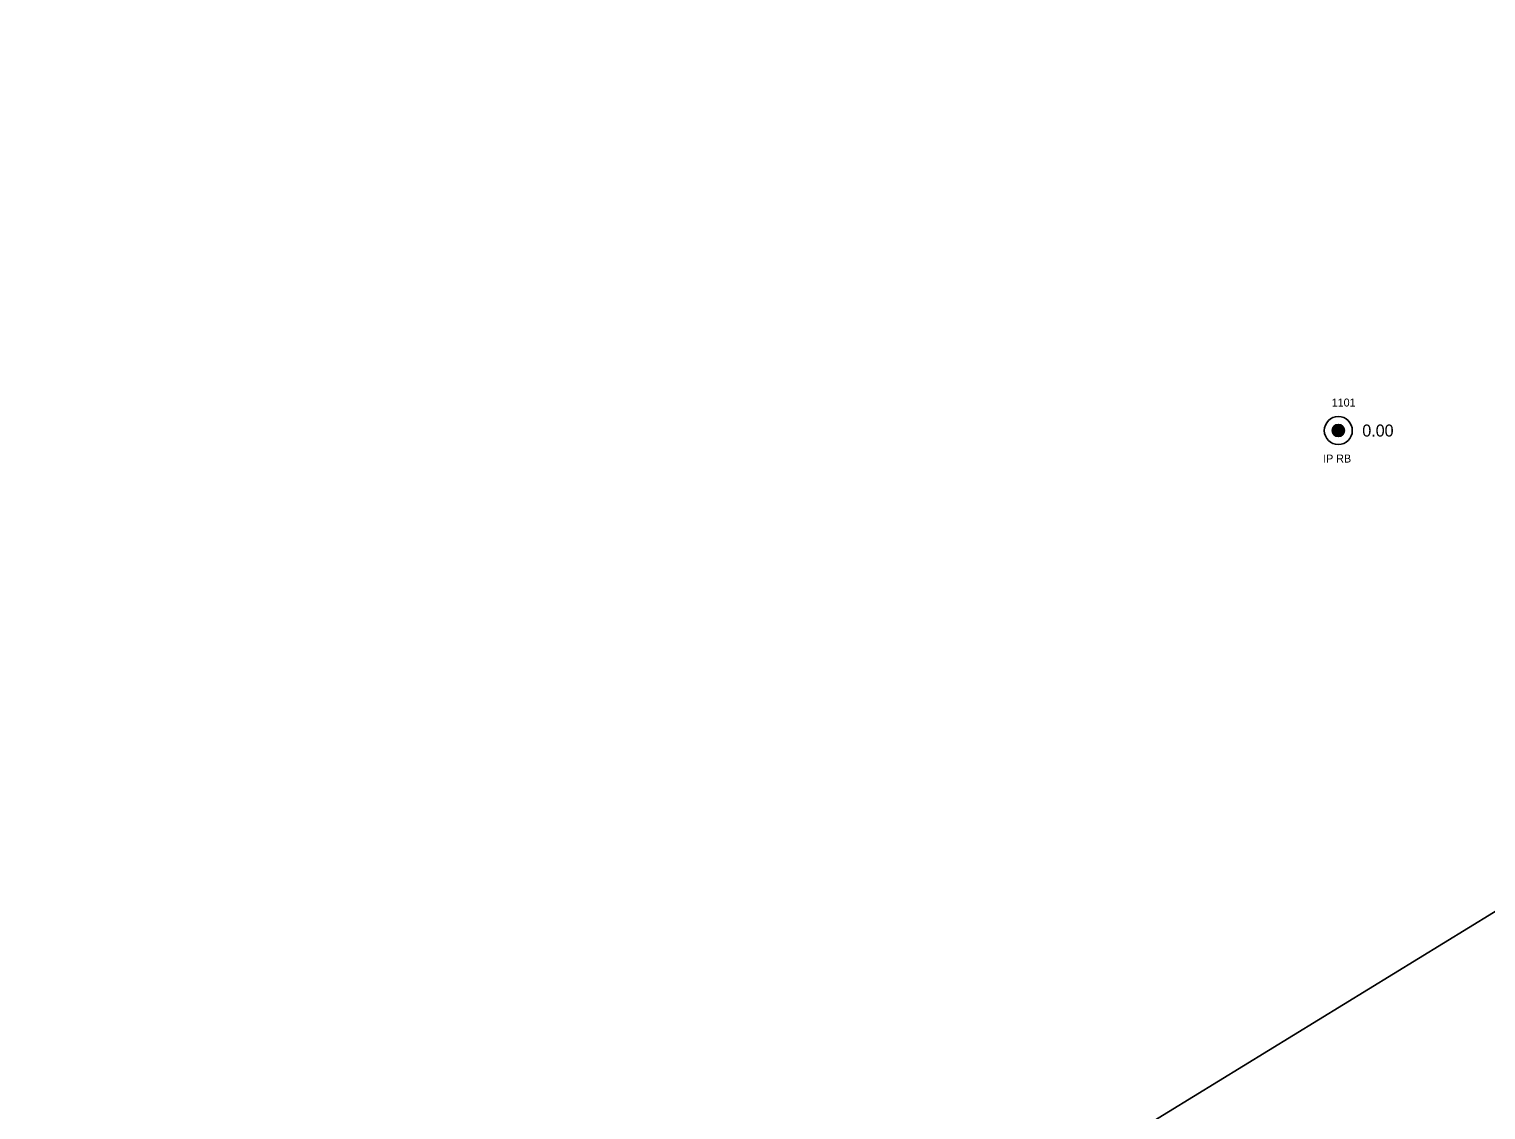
# Model space of a CAD drawing. Extents: x 1575382 to 1578175, y 1099175 to 1101955.
# Drawn here: x 1575942.3 to 1576124.3, y 1099553 to 1099688.1 of the extents above; entities that cross this region are included whole.
import ezdxf

# ---------------------------------------------------------------- set-up
doc = ezdxf.new("R2010")
doc.units = 0
for name, color, linetype in [('RD_EX_DV_Prop_txCode', 7, 'Continuous'), ('RD_EX_DV_PropPin', 7, 'Continuous'), ('RD_EX_TX_DV_Prop_ELEV', 7, 'Continuous'), ('RD_EX_UT', 7, 'Continuous'), ('RD_SMD_Locator', 7, 'Continuous')]:
    doc.layers.add(name, color=color, linetype=linetype)

msp = doc.modelspace()

# ---------------------------------------------------------------- linework, layer by layer
at = {"layer": 'RD_EX_DV_PropPin'}
for p, q in [((1576105.13, 1099637.72), (1576105.13, 1099638.11)), ((1576105.17, 1099637.62), (1576105.17, 1099638.22)), ((1576105.2, 1099637.55), (1576105.2, 1099638.29)), ((1576105.24, 1099637.49), (1576105.24, 1099638.35)), ((1576105.27, 1099637.44), (1576105.27, 1099638.39)), ((1576105.31, 1099637.4), (1576105.31, 1099638.43)), ((1576105.34, 1099637.37), (1576105.34, 1099638.47)), ((1576105.38, 1099637.34), (1576105.38, 1099638.5)), ((1576105.41, 1099637.31), (1576105.41, 1099638.53)), ((1576105.45, 1099637.28), (1576105.45, 1099638.55)), ((1576105.48, 1099637.26), (1576105.48, 1099638.58)), ((1576105.52, 1099637.24), (1576105.52, 1099638.59)), ((1576105.55, 1099637.23), (1576105.55, 1099638.61)), ((1576105.59, 1099637.21), (1576105.59, 1099638.63)), ((1576105.62, 1099637.2), (1576105.62, 1099638.64)), ((1576105.66, 1099637.19), (1576105.66, 1099638.65)), ((1576105.69, 1099637.18), (1576105.69, 1099638.66)), ((1576105.73, 1099637.17), (1576105.73, 1099638.67)), ((1576105.76, 1099637.17), (1576105.76, 1099638.67)), ((1576105.8, 1099637.16), (1576105.8, 1099638.68)), ((1576105.83, 1099637.16), (1576105.83, 1099638.68)), ((1576105.87, 1099637.16), (1576105.87, 1099638.68)), ((1576105.9, 1099637.16), (1576105.9, 1099638.68)), ((1576105.94, 1099637.16), (1576105.94, 1099638.68)), ((1576105.97, 1099637.17), (1576105.97, 1099638.67)), ((1576106.01, 1099637.17), (1576106.01, 1099638.67)), ((1576106.04, 1099637.18), (1576106.04, 1099638.66)), ((1576106.08, 1099637.19), (1576106.08, 1099638.65)), ((1576106.11, 1099637.2), (1576106.11, 1099638.64)), ((1576106.15, 1099637.21), (1576106.15, 1099638.63)), ((1576106.18, 1099637.23), (1576106.18, 1099638.61)), ((1576106.22, 1099637.24), (1576106.22, 1099638.59)), ((1576106.25, 1099637.26), (1576106.25, 1099638.58)), ((1576106.29, 1099637.28), (1576106.29, 1099638.55)), ((1576106.32, 1099637.31), (1576106.32, 1099638.53)), ((1576106.36, 1099637.34), (1576106.36, 1099638.5)), ((1576106.39, 1099637.37), (1576106.39, 1099638.47)), ((1576106.43, 1099637.4), (1576106.43, 1099638.43)), ((1576106.46, 1099637.44), (1576106.46, 1099638.39)), ((1576106.5, 1099637.49), (1576106.5, 1099638.35)), ((1576106.53, 1099637.55), (1576106.53, 1099638.29)), ((1576106.57, 1099637.62), (1576106.57, 1099638.22)), ((1576106.6, 1099637.72), (1576106.6, 1099638.11))]:
    msp.add_line(p, q, dxfattribs=at)
for radius in [1.75, 0.761]:
    msp.add_circle((1576105.87, 1099637.92), radius, dxfattribs=at)
at = {"layer": 'RD_EX_UT'}
msp.add_line((1575942.28, 1099465.48), (1576305.27, 1099688.09), dxfattribs=at)
at = {"layer": 'RD_SMD_Locator'}
msp.add_circle((1576105.87, 1099637.92), 0.15, dxfattribs=at)

# ---------------------------------------------------------------- texts
at = {"layer": 'RD_EX_DV_Prop_txCode'}
for s, p in [('1101', (1576105.05, 1099640.92)), ('IP RB', (1576103.98, 1099633.92))]:
    msp.add_text(s, height=1, dxfattribs=at).set_placement(p)
at = {"layer": 'RD_EX_TX_DV_Prop_ELEV'}
msp.add_text('0.00', height=1.5, dxfattribs=at).set_placement((1576108.87, 1099637.17))

doc.saveas('drawing.dxf')
